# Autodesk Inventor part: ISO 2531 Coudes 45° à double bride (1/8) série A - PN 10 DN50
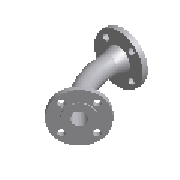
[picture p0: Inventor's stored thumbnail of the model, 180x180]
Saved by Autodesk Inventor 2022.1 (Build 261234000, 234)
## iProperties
Created: 2021-02
Part Number: ISO 2531 Coudes 45° à double bride (1/8) série A - PN 10 DN50
Material: Fonte, ductile
Description: Tuyaux en fonte ductile, raccords, accessoires et liaisons pour eau et gaz - Coudes à double bride 45° (1/8) série A - PN 10
Document SubType Name: Modeling
Standard: ISO 2531
Designer: Fabian
Standard Revision: Fifth edition  1998-08-15
Standards Organization: ISO
Language: fr-FR
Size Designation: DN50
Categories: <MemberInstance><Categories><Category DisplayName="Tubes et tuyaux" InternalName="4347fa0f-2144-441d-94cd-e3e15c92b736" Mnemonic="TUBEANDPIPE"><CategoryParamete
Density: 7.15 g/cm^3
Appearance: Fonte grise
IsCustomPart: 0
NAME: PIPING: ISO 2531 45 Deg Double Flanged Bend - PN 10
DATA: <meta><inlinegroups number="0" deflen="0"></inlinegroups><connections number="2"></connections><angles><a>2.35619449019234</a></angles></meta>
Author: Fabian
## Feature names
1. Revolution1
2. Sweep1
3. Revolution2
4. Extrusion1
5. Circular Pattern1
6. Extrusion2
7. Circular Pattern2
## Parameters: D = 165 mm, K1 = 125 mm, L2 = 19 mm, N3 = 84 mm, f1 = 3 mm, d11 = 99 mm, e = 7 mm, C7 = 19 mm, d0 = 165 mm, d1 = 84 mm, d2 = 7 mm, d3 = 99 mm, d4 = 3 mm, d5 = 15 deg, d7 = 55 mm, d15 = 90 deg, d9 = 7 mm, d10 = 3 mm, d13 = 99 mm, d14 = 165 mm, d16 = 84 mm, d17 = 55 mm, d18 = 7 mm, d19 = 0, d27 = 90 deg, d20 = 125 mm, d21 = 16 mm, d22 = 0, d24 = 360 deg, d25 = 125 mm, d26 = 16 mm, d28 = 0, d30 = 360 deg, d31 = 19 mm, d32 = 19 mm, d34 = 135 deg, d36 = 15 deg, d37 = 19 mm, d38 = 45 deg, d39 = 19 mm, d41 = 45 deg, d51 = 0, Size_Designation = 12.345 mm
